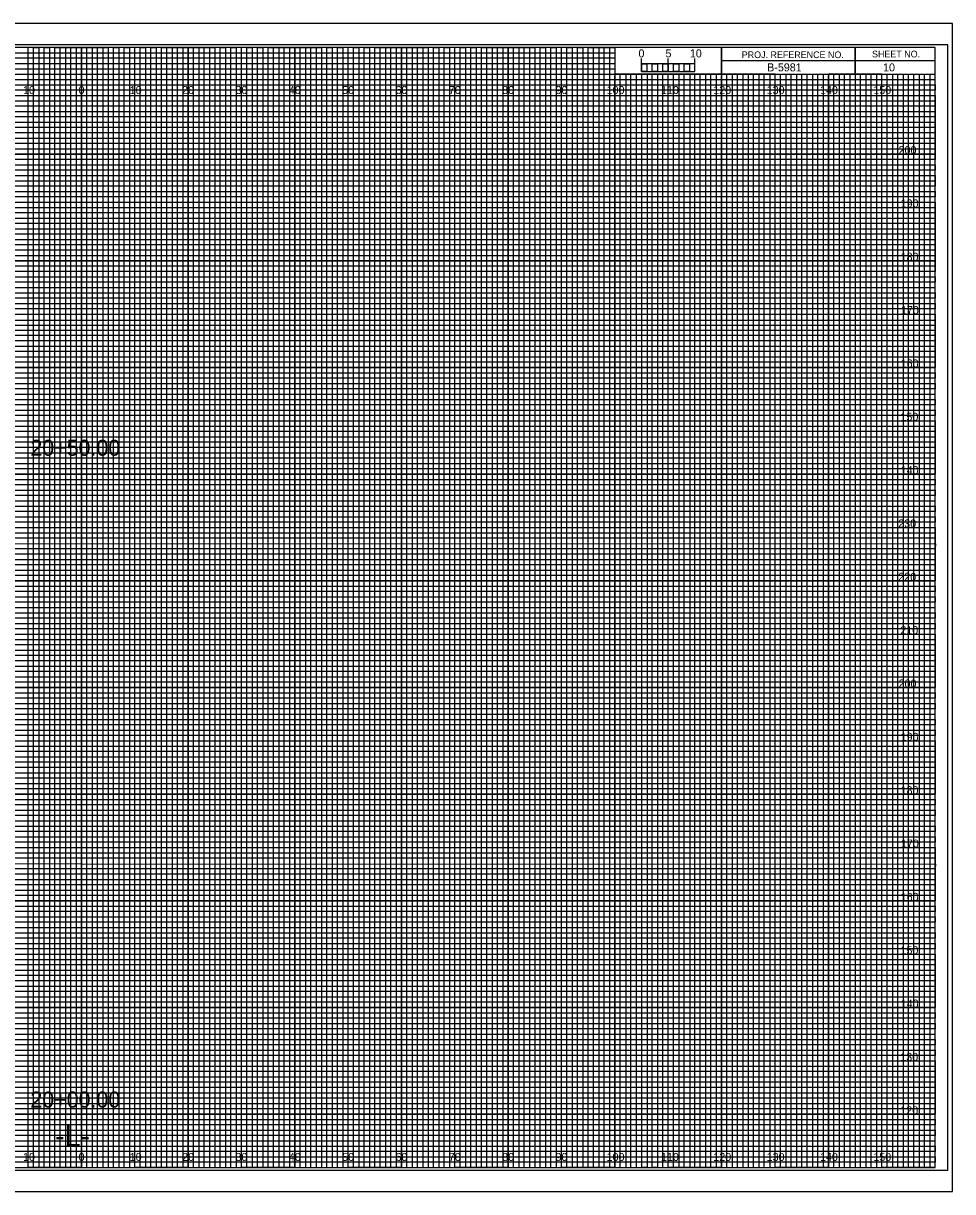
# Model space of a CAD drawing. Extents: x -13 to 323, y -5 to 1754.
# Drawn here: x 149.1 to 323.3, y 1315.5 to 1534.5 of the extents above; entities that cross this region are included whole.
import ezdxf

# ---------------------------------------------------------------- set-up
doc = ezdxf.new("R2010")
doc.units = 0
for name, color, linetype in [('Exist Cross Section Cell', 7, 'Continuous'), ('Exist XS Center Line Elevation Label', 7, 'Continuous'), ('Exist XS Ground Line', 7, 'Continuous'), ('Prop CMT Concrete Structures', 7, 'Continuous'), ('Prop CMT Guardrail Graphics', 7, 'Continuous'), ('Prop CMT Pvmt Course 1', 7, 'Continuous'), ('Prop CMT Pvmt Course 2', 7, 'Continuous'), ('Prop CMT Pvmt Course 3', 7, 'Continuous'), ('Prop CMT Pvmt Surface', 7, 'Continuous'), ('Prop CMT Shld Paved Course 1', 7, 'Continuous'), ('Prop CMT Shld Paved Course 2', 7, 'Continuous'), ('Prop CMT Shld Paved Course 3', 7, 'Continuous'), ('Prop CMT Subgrade Earthwork', 7, 'Continuous'), ('Prop XS Ditch Standard Text', 7, 'Continuous'), ('Prop XS SE Text', 7, 'Continuous'), ('Prop XS Side Slope Text', 7, 'Continuous'), ('Scratch_Level_0', 7, 'Continuous')]:
    doc.layers.add(name, color=color, linetype=linetype)

msp = doc.modelspace()

# ---------------------------------------------------------------- linework, layer by layer
at = {"layer": 'Exist XS Center Line Elevation Label'}
for points in [[(145, 1320), (155, 1320), (155, 1530), (165, 1530), (165, 1320), (175, 1320), (175, 1530), (185, 1530), (185, 1320), (195, 1320), (195, 1530), (205, 1530), (205, 1320), (215, 1320), (215, 1530), (225, 1530), (225, 1320), (235, 1320), (235, 1530), (245, 1530), (245, 1320), (255, 1320), (255, 1530), (259.93, 1530), (260, 1530), (260, 1525), (264.99, 1525), (264.99, 1320), (275, 1320), (275, 1525), (285, 1525), (285, 1320), (295, 1320), (295, 1525), (305, 1525), (305, 1320), (315, 1320), (315, 1525)], [(0, 1525), (275, 1525)], [(0, 1505), (320, 1505), (320, 1515), (0, 1515)], [(0, 1485), (320, 1485), (320, 1495), (0, 1495)], [(0, 1465), (320, 1465), (320, 1475), (0, 1475)], [(0, 1445), (320, 1445), (320, 1455), (0, 1455)], [(0, 1425), (320, 1425), (320, 1435), (0, 1435)], [(0, 1405), (320, 1405), (320, 1415), (0, 1415)], [(0, 1385), (320, 1385), (320, 1395), (0, 1395)], [(0, 1365), (320, 1365), (320, 1375), (0, 1375)], [(0, 1345), (320, 1345), (320, 1355), (0, 1355)], [(0, 1325), (320, 1325), (320, 1335), (0, 1335)]]:
    msp.add_lwpolyline(points, dxfattribs=at)
at = {"layer": 'Exist XS Ground Line'}
for p, q in [((150, 1530), (140, 1530)), ((150, 1320), (150, 1530)), ((170, 1530), (160, 1530)), ((160, 1530), (160, 1320)), ((170, 1320), (170, 1530)), ((190, 1530), (180, 1530)), ((180, 1530), (180, 1320)), ((190, 1320), (190, 1530)), ((210, 1530), (200, 1530)), ((200, 1530), (200, 1320)), ((210, 1320), (210, 1530)), ((230, 1530), (220, 1530)), ((220, 1530), (220, 1320)), ((230, 1320), (230, 1530)), ((250, 1530), (240, 1530)), ((240, 1530), (240, 1320)), ((250, 1320), (250, 1530)), ((260, 1530), (260, 1320)), ((270, 1320), (270, 1525)), ((290, 1525), (280, 1525)), ((280, 1525), (280, 1320)), ((290, 1320), (290, 1525)), ((310, 1525), (300, 1525)), ((300, 1525), (300, 1320)), ((310, 1320), (310, 1525)), ((160, 1320), (150, 1320)), ((180, 1320), (170, 1320)), ((200, 1320), (190, 1320)), ((220, 1320), (210, 1320)), ((240, 1320), (230, 1320)), ((260, 1320), (250, 1320)), ((280, 1320), (270, 1320)), ((300, 1320), (290, 1320)), ((320, 1320), (310, 1320)), ((320, 1320), (320, 1320))]:
    msp.add_line(p, q, dxfattribs=at)
for points in [[(0, 1520), (320, 1520), (320, 1510), (0, 1510)], [(0, 1500), (320, 1500), (320, 1490), (0, 1490)], [(0, 1480), (320, 1480), (320, 1470), (0, 1470)], [(0, 1460), (320, 1460), (320, 1450), (0, 1450)], [(0, 1440), (320, 1440), (320, 1430), (0, 1430)], [(0, 1420), (320, 1420), (320, 1410), (0, 1410)], [(0, 1400), (320, 1400), (320, 1390), (0, 1390)], [(0, 1380), (320, 1380), (320, 1370), (0, 1370)], [(0, 1360), (320, 1360), (320, 1350), (0, 1350)], [(0, 1340), (320, 1340), (320, 1330), (0, 1330)]]:
    msp.add_lwpolyline(points, dxfattribs=at)
at = {"layer": 'Prop CMT Pvmt Course 1'}
for p, q in [((323.3, 1534.5), (-13.4, 1534.5)), ((-13.4, 1315.5), (323.3, 1315.5))]:
    msp.add_line(p, q, dxfattribs=at)
at = {"layer": 'Prop CMT Pvmt Course 2'}
msp.add_lwpolyline([(-13.4, 1315.5), (323.3, 1315.5), (323.3, 1534.5), (-13.4, 1534.5)], close=True, dxfattribs=at)
at = {"layer": 'Prop CMT Pvmt Course 3'}
msp.add_lwpolyline([(-10.8, 1319.5), (322.4, 1319.5), (322.4, 1530.5), (-10.8, 1530.5)], close=True, dxfattribs=at)
at = {"layer": 'Prop CMT Shld Paved Course 1'}
for p, q in [((305, 1530), (305, 1525)), ((305, 1525), (305, 1530)), ((280, 1527.5), (280, 1525)), ((320, 1527.49), (280, 1527.49)), ((280, 1525), (320, 1525))]:
    msp.add_line(p, q, dxfattribs=at)
for points in [[(320, 1530), (0, 1530), (0, 1320), (320, 1320)], [(280, 1530), (260, 1530), (260, 1525.03), (280, 1525.03)], [(320, 1530), (280, 1530), (280, 1525), (320, 1525)]]:
    msp.add_lwpolyline(points, close=True, dxfattribs=at)
at = {"layer": 'Prop CMT Shld Paved Course 2'}
for p, q in [((267, 1525), (266.01, 1525)), ((266.01, 1525), (266.01, 1320)), ((267, 1320), (267, 1525)), ((269, 1525), (268, 1525)), ((268, 1525), (268, 1320)), ((269, 1320), (269, 1525)), ((266.01, 1320), (265, 1320)), ((268, 1320), (267, 1320))]:
    msp.add_line(p, q, dxfattribs=at)
for points in [[(150, 1320), (151, 1320), (151, 1530), (152, 1530), (152, 1320)], [(152, 1320), (153, 1320), (153, 1530), (154, 1530), (154, 1320)], [(155, 1320), (156, 1320), (156, 1530), (157, 1530), (157, 1320)], [(157, 1320), (158, 1320), (158, 1530), (159, 1530), (159, 1320)], [(160, 1320), (161, 1320), (161, 1530), (162, 1530), (162, 1320)], [(162, 1320), (163, 1320), (163, 1530), (164, 1530), (164, 1320)], [(165, 1320), (166, 1320), (166, 1530), (167, 1530), (167, 1320)], [(167, 1320), (168, 1320), (168, 1530), (169, 1530), (169, 1320)], [(170, 1320), (171, 1320), (171, 1530), (172, 1530), (172, 1320)], [(172, 1320), (173, 1320), (173, 1530), (174, 1530), (174, 1320)], [(175, 1320), (176, 1320), (176, 1530), (177, 1530), (177, 1320)], [(177, 1320), (178, 1320), (178, 1530), (179, 1530), (179, 1320)], [(180, 1320), (181, 1320), (181, 1530), (182, 1530), (182, 1320)], [(182, 1320), (183, 1320), (183, 1530), (184, 1530), (184, 1320)], [(185, 1320), (186, 1320), (186, 1530), (187, 1530), (187, 1320)], [(187, 1320), (188, 1320), (188, 1530), (189, 1530), (189, 1320)], [(190, 1320), (191, 1320), (191, 1530), (192, 1530), (192, 1320)], [(192, 1320), (193, 1320), (193, 1530), (194, 1530), (194, 1320)], [(195, 1320), (196, 1320), (196, 1530), (197, 1530), (197, 1320)], [(197, 1320), (198, 1320), (198, 1530), (199, 1530), (199, 1320)], [(200, 1320), (201, 1320), (201, 1530), (202, 1530), (202, 1320)], [(202, 1320), (203, 1320), (203, 1530), (204, 1530), (204, 1320)], [(205, 1320), (206, 1320), (206, 1530), (207, 1530), (207, 1320)], [(207, 1320), (208, 1320), (208, 1530), (209, 1530), (209, 1320)], [(210, 1320), (211, 1320), (211, 1530), (212, 1530), (212, 1320)], [(212, 1320), (213, 1320), (213, 1530), (214, 1530), (214, 1320)], [(215, 1320), (216, 1320), (216, 1530), (217, 1530), (217, 1320)], [(217, 1320), (218, 1320), (218, 1530), (219, 1530), (219, 1320)], [(220, 1320), (221, 1320), (221, 1530), (222, 1530), (222, 1320)], [(222, 1320), (223, 1320), (223, 1530), (224, 1530), (224, 1320)], [(225, 1320), (226, 1320), (226, 1530), (227, 1530), (227, 1320)], [(227, 1320), (228, 1320), (228, 1530), (229, 1530), (229, 1320)], [(230, 1320), (231, 1320), (231, 1530), (232, 1530), (232, 1320)], [(232, 1320), (233, 1320), (233, 1530), (234, 1530), (234, 1320)], [(235, 1320), (236, 1320), (236, 1530), (237, 1530), (237, 1320)], [(237, 1320), (238, 1320), (238, 1530), (239, 1530), (239, 1320)], [(240, 1320), (241, 1320), (241, 1530), (242, 1530), (242, 1320)], [(242, 1320), (243, 1320), (243, 1530), (244, 1530), (244, 1320)], [(245, 1320), (246, 1320), (246, 1530), (247, 1530), (247, 1320)], [(247, 1320), (248, 1320), (248, 1530), (249, 1530), (249, 1320)], [(250, 1320), (251, 1320), (251, 1530), (252, 1530), (252, 1320)], [(252, 1320), (253, 1320), (253, 1530), (254, 1530), (254, 1320)], [(255, 1320), (256, 1320), (256, 1530), (257, 1530), (257, 1320)], [(257, 1320), (258, 1320), (258, 1530), (259, 1530), (259, 1320)], [(260, 1320), (261, 1320), (261, 1525), (262.02, 1525), (262.02, 1320)], [(262, 1320), (263, 1320), (263, 1525), (263.99, 1525), (263.99, 1320)], [(270, 1320), (270.98, 1320), (270.98, 1525), (272, 1525), (272, 1320)], [(272, 1320), (273, 1320), (273, 1525), (274.05, 1525), (274.05, 1320)], [(275, 1320), (276, 1320), (276, 1525), (277, 1525), (277, 1320)], [(277, 1320), (278, 1320), (278, 1525), (279, 1525), (279, 1320)], [(280, 1320), (281, 1320), (281, 1525), (282, 1525), (282, 1320)], [(282, 1320), (283, 1320), (283, 1525), (284, 1525), (284, 1320)], [(285, 1320), (286, 1320), (286, 1525), (287, 1525), (287, 1320)], [(287, 1320), (288, 1320), (288, 1525), (289, 1525), (289, 1320)], [(290, 1320), (291, 1320), (291, 1525), (292, 1525), (292, 1320)], [(292, 1320), (293, 1320), (293, 1525), (294, 1525), (294, 1320)], [(295, 1320), (296, 1320), (296, 1525), (297, 1525), (297, 1320)], [(297, 1320), (298, 1320), (298, 1525), (299, 1525), (299, 1320)], [(300, 1320), (301, 1320), (301, 1525), (302, 1525), (302, 1320)], [(302, 1320), (303, 1320), (303, 1525), (304, 1525), (304, 1320)], [(305, 1320), (306, 1320), (306, 1525), (307, 1525), (307, 1320)], [(307, 1320), (308, 1320), (308, 1525), (309, 1525), (309, 1320)], [(310, 1320), (311, 1320), (311, 1525), (312, 1525), (312, 1320)], [(312, 1320), (313, 1320), (313, 1525), (314, 1525), (314, 1320)], [(315, 1320), (316, 1320), (316, 1525), (317, 1525), (317, 1320)], [(317, 1320), (318, 1320), (318, 1525), (319, 1525), (319, 1320)]]:
    msp.add_lwpolyline(points, dxfattribs=at)
at = {"layer": 'Prop CMT Shld Paved Course 3'}
for p, q in [((265, 1525.49), (265, 1527.9)), ((265, 1526.9), (265, 1527.9)), ((270, 1525.49), (270, 1527.9)), ((275, 1525.49), (275, 1527.9)), ((275, 1526.9), (275, 1527.9))]:
    msp.add_line(p, q, dxfattribs=at)
for points in [[(275, 1526.9), (265, 1526.9), (265, 1525.49), (275, 1525.49)], [(265, 1526.9), (266, 1526.9), (266, 1525.49), (265, 1525.49)], [(267, 1526.9), (268, 1526.9), (268, 1525.49), (267, 1525.49)], [(269, 1526.9), (270, 1526.9), (270, 1525.49), (269, 1525.49)], [(271, 1526.9), (272, 1526.9), (272, 1525.49), (271, 1525.49)], [(273, 1526.9), (274, 1526.9), (274, 1525.49), (273, 1525.49)]]:
    msp.add_lwpolyline(points, close=True, dxfattribs=at)
at = {"layer": 'Prop CMT Subgrade Earthwork'}
for p, q in [((150, 1320), (150, 1530)), ((160, 1320), (160, 1530)), ((170, 1320), (170, 1530)), ((180, 1320), (180, 1530)), ((190, 1320), (190, 1530)), ((200, 1320), (200, 1530)), ((210, 1320), (210, 1530)), ((220, 1320), (220, 1530)), ((230, 1320), (230, 1530)), ((240, 1320), (240, 1530)), ((250, 1320), (250, 1530)), ((260, 1320), (260, 1524.69)), ((270, 1320), (270, 1524.69)), ((280, 1320), (280, 1524.69)), ((290, 1320), (290, 1524.69)), ((300, 1320), (300, 1524.69)), ((310, 1320), (310, 1524.69)), ((0, 1520), (320, 1520)), ((0, 1510), (320, 1510)), ((0, 1500), (320, 1500)), ((0, 1490), (320, 1490)), ((0, 1480), (320, 1480)), ((0, 1470), (320, 1470)), ((0, 1460), (320, 1460)), ((0, 1450), (320, 1450)), ((0, 1440), (320, 1440)), ((0, 1430), (320, 1430)), ((0, 1420), (320, 1420)), ((0, 1410), (320, 1410)), ((0, 1400), (320, 1400)), ((0, 1390), (320, 1390)), ((0, 1380), (320, 1380)), ((0, 1370), (320, 1370)), ((0, 1360), (320, 1360)), ((0, 1350), (320, 1350)), ((0, 1340), (320, 1340)), ((0, 1330), (320, 1330))]:
    msp.add_line(p, q, dxfattribs=at)
at = {"layer": 'Scratch_Level_0'}
for p, q in [((0, 1529), (260, 1529)), ((260, 1529), (260, 1527.98)), ((260, 1527.98), (0, 1527.98)), ((0, 1527), (260, 1527)), ((260, 1527), (260, 1525.89)), ((260, 1525.89), (0, 1525.89)), ((0, 1524), (320, 1524))]:
    msp.add_line(p, q, dxfattribs=at)
for points in [[(0, 1523), (270, 1523), (320, 1523), (320, 1522), (0, 1522)], [(0, 1521), (320, 1521), (320, 1519), (0, 1519)], [(0, 1518), (320, 1518), (320, 1517), (0, 1516.98)], [(0, 1516), (320, 1516), (320, 1514), (0, 1514)], [(0, 1513), (320, 1513), (320, 1512), (0, 1512)], [(0, 1511), (320, 1511), (320, 1509), (0, 1509)], [(0, 1508), (320, 1508), (320, 1507), (0, 1507)], [(0, 1506), (320, 1506), (320, 1504), (0, 1504)], [(0, 1503), (320, 1503), (320, 1502), (0, 1502)], [(0, 1501), (320, 1501), (320, 1499), (0, 1499)], [(0, 1498), (320, 1498), (320, 1497), (0, 1497)], [(0, 1496), (320, 1496), (320, 1493.95), (320, 1493), (320, 1492), (0, 1492)], [(0, 1494), (320, 1494), (320, 1493), (0, 1493)], [(0, 1491), (320, 1491), (320, 1489), (0, 1489.03)], [(0, 1489.03), (320, 1489), (320, 1488), (0, 1488)], [(0, 1487), (320, 1487), (320, 1486), (0, 1486)], [(0, 1484), (320, 1484), (320, 1483), (0, 1483)], [(0, 1482), (320, 1482), (320, 1481), (0, 1481)], [(-0.07, 1478.89), (320, 1478.89), (320, 1477.88), (-0.07, 1477.88)], [(0, 1477), (320, 1477), (320, 1476), (0, 1476)], [(0, 1474), (320, 1474), (320, 1473), (0, 1473)], [(0, 1472), (320, 1472), (320, 1471), (0, 1471)], [(0, 1469), (320, 1469), (320, 1468), (0, 1468)], [(0, 1467), (320, 1467), (320, 1466), (0, 1466)], [(0, 1464), (320, 1464), (320, 1463), (0, 1463)], [(0, 1462), (320, 1462), (320, 1461), (0, 1461)], [(0, 1459), (320, 1459), (319.99, 1457.98), (0, 1458)], [(0, 1457), (320, 1457), (320, 1456), (0, 1456)], [(0, 1454), (320, 1454), (320, 1453), (0, 1453)], [(0, 1452), (320, 1452), (320, 1451), (0, 1451)], [(0, 1449), (320, 1449), (320, 1448), (0, 1448)], [(0, 1447), (320, 1447), (320, 1446), (0, 1446)], [(0, 1444), (320, 1444), (320, 1443), (0, 1443)], [(0, 1442), (320, 1442), (320, 1441), (0, 1441)], [(0, 1439), (320, 1439), (320, 1438), (0, 1438)], [(0, 1436.99), (320.07, 1436.91), (320, 1436), (0, 1436)], [(0, 1434), (320, 1434), (320, 1433), (0, 1433)], [(0, 1432), (320, 1432), (320, 1431), (0, 1431)], [(0, 1429), (320, 1429), (320, 1428), (0, 1428)], [(0, 1427), (320, 1427), (320, 1426), (0, 1426)], [(0, 1424), (320, 1424), (320, 1423), (0, 1423)], [(0, 1422), (320, 1422), (320, 1421), (0, 1421)], [(0, 1419), (320, 1419), (320, 1418), (0, 1418)], [(0, 1417), (320, 1417), (320, 1416), (0, 1416)], [(0, 1414), (320, 1414), (320, 1413), (0, 1413)], [(0, 1412), (320, 1412), (320, 1411), (0, 1411)], [(0, 1409), (320, 1409), (320, 1408), (0, 1408)], [(0, 1407), (320, 1407), (320, 1406), (0, 1406)], [(0, 1404), (320, 1404), (320, 1403), (0, 1403)], [(0, 1402), (320, 1402), (320, 1401), (0, 1401)], [(0, 1399), (320, 1399), (319.99, 1397.98), (0, 1398)], [(0, 1397), (320, 1397), (320, 1396), (0, 1396)], [(0, 1394), (320, 1394), (320, 1393), (0, 1393)], [(0, 1392), (320, 1392), (320, 1391), (0, 1391)], [(0, 1389), (320, 1389), (320, 1388), (0, 1388)], [(0, 1387), (320, 1387), (320, 1386), (0, 1386)], [(0, 1384), (320, 1384), (320, 1383), (0, 1383)], [(0, 1382), (320, 1382), (320, 1381), (0, 1381)], [(0, 1379), (320, 1379), (320, 1378), (0, 1378)], [(0, 1376.99), (320.07, 1376.91), (320, 1376), (0, 1376)], [(0, 1374), (320, 1374), (320, 1373), (0, 1373)], [(0, 1372), (320, 1372), (320, 1371), (0, 1371)], [(0, 1369), (320, 1369), (320, 1368), (0, 1368)], [(0, 1367), (320, 1367), (320, 1366), (0, 1366)], [(0, 1364), (320, 1364), (320, 1363), (0, 1363)], [(0, 1362), (320, 1362), (320, 1361), (0, 1361)], [(0, 1359), (320, 1359), (320, 1358), (0, 1358)], [(0, 1357), (320, 1357), (320, 1356), (0, 1356)], [(0, 1354), (320, 1354), (320, 1353), (0, 1353)], [(0, 1352), (320, 1352), (320, 1351), (0, 1351)], [(0, 1349), (320, 1349), (320, 1348), (0, 1348)], [(0, 1347), (320, 1347), (320, 1346), (0, 1346)], [(0, 1344), (320, 1344), (320, 1343), (0, 1343)], [(0, 1342), (320, 1342), (320, 1341), (0, 1341)], [(0, 1339), (320, 1339), (320, 1338), (0, 1338)], [(0, 1337), (320, 1337), (320, 1336), (0, 1336)], [(0, 1334), (320, 1334), (320, 1333), (0, 1333)], [(0, 1332), (320, 1332), (320, 1331), (0, 1331)], [(0, 1329), (320, 1329), (320, 1328), (0, 1328)], [(0, 1327), (320, 1327), (320, 1326), (0, 1326)], [(0, 1324), (320, 1324), (320, 1323), (0, 1323)], [(0, 1322), (320, 1322), (320, 1321), (0, 1321)]]:
    msp.add_lwpolyline(points, dxfattribs=at)

# ---------------------------------------------------------------- texts
at = {"layer": 'Exist Cross Section Cell'}
for s, p in [('200', (313.17, 1510)), ('190', (313.57, 1500)), ('180', (313.55, 1490)), ('170', (313.61, 1480)), ('160', (313.57, 1470)), ('150', (313.52, 1460)), ('140', (313.57, 1450)), ('230', (313.11, 1440)), ('220', (313.12, 1430)), ('210', (313.5, 1420)), ('200', (313.17, 1410)), ('190', (313.57, 1400)), ('180', (313.55, 1390)), ('170', (313.61, 1380)), ('160', (313.57, 1370)), ('150', (313.52, 1360)), ('140', (313.57, 1350)), ('130', (313.49, 1340)), ('120', (313.5, 1330))]:
    msp.add_text(s, height=1.5, dxfattribs=at).set_placement(p)
at = {"layer": 'Prop CMT Concrete Structures'}
msp.add_text('10', height=1.5, dxfattribs=at).set_placement((310.26, 1525.5))
at = {"layer": 'Prop CMT Guardrail Graphics'}
for s, p in [('5', (269.47, 1528.12)), ('10', (274.04, 1528.12))]:
    msp.add_text(s, height=1.5, dxfattribs=at).set_placement(p)
at = {"layer": 'Prop CMT Pvmt Surface'}
for s, p in [('20+50.00', (150.41, 1453.45)), ('20+00.00', (150.41, 1331.26))]:
    msp.add_text(s, height=3, dxfattribs=at).set_placement(p)
at = {"layer": 'Prop CMT Shld Paved Course 1'}
for s, p in [('PROJ. REFERENCE NO.', (283.77, 1527.99)), ('SHEET NO.', (308.19, 1528.12))]:
    msp.add_text(s, height=1.25, dxfattribs=at).set_placement(p)
at = {"layer": 'Prop CMT Shld Paved Course 3'}
msp.add_text('0', height=1.5, dxfattribs=at).set_placement((264.41, 1528.12))
at = {"layer": 'Prop XS Ditch Standard Text'}
for s, p in [('10', (149.04, 1521.25)), ('0', (159.45, 1521.25)), ('0', (159.45, 1521.25)), ('10', (169.04, 1521.25)), ('20', (178.86, 1521.25)), ('30', (188.86, 1521.25)), ('40', (198.86, 1521.25)), ('50', (208.86, 1521.25)), ('60', (218.86, 1521.25)), ('70', (228.86, 1521.25)), ('80', (238.86, 1521.25)), ('90', (248.86, 1521.25)), ('100', (258.44, 1521.25)), ('110', (268.62, 1521.25)), ('120', (278.44, 1521.25)), ('130', (288.44, 1521.25)), ('140', (298.44, 1521.25)), ('150', (308.44, 1521.25)), ('10', (149.04, 1321.25)), ('0', (159.45, 1321.25)), ('0', (159.45, 1321.25)), ('10', (169.04, 1321.25)), ('20', (178.86, 1321.25)), ('30', (188.86, 1321.25)), ('40', (198.86, 1321.25)), ('50', (208.86, 1321.25)), ('60', (218.86, 1321.25)), ('70', (228.86, 1321.25)), ('80', (238.86, 1321.25)), ('90', (248.86, 1321.25)), ('100', (258.44, 1321.25)), ('110', (268.62, 1321.25)), ('120', (278.44, 1321.25)), ('130', (288.44, 1321.25)), ('140', (298.44, 1321.25)), ('150', (308.44, 1321.25))]:
    msp.add_text(s, height=1.5, dxfattribs=at).set_placement(p)
at = {"layer": 'Prop XS SE Text'}
msp.add_text('-L-', height=4, dxfattribs=at).set_placement((155.06, 1324))
at = {"layer": 'Prop XS Side Slope Text'}
msp.add_text('B-5981', height=1.5, dxfattribs=at).set_placement((288.53, 1525.5))

doc.saveas('drawing.dxf')
